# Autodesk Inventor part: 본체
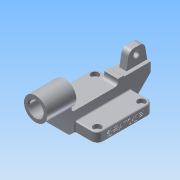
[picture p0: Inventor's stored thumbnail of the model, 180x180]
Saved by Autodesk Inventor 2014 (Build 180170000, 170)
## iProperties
Created: 2017-10
Part Number: 본체
Material: 알루미늄 6061
Document SubType Name: Modeling
Designer: mduedu
Density: 2.71 g/cm^3
Mass: 97.8104 g
Surface Area: 126.629 cm^2
Volume: 36.0924 cm^3
Appearance: 알루미늄 - 평지
Author: mduedu
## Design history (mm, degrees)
sketch "스케치1"
  geometry: L1 (0, 0)-(-90, 0); L2 (-90, 0)-(-90, 20); L3 (-90, 20)-(0, 20); L4 (0, 20)-(0, 0)
  constraints: 8 end point, 2 parallel, 1 horizontal, 1 perpendicular
  dimensions: "d0" = 90 distance of L2.end L3.end; "d2" = 20 distance of L1.end L2.end
extrude "돌출1" new body sketch "스케치1" stored distance "d3" = 12; taper "d4" = 0 deg
chamfer "모따기1" distance "d5" = 20; stored, may be unused: second distance "d6" = 2, angle "d7" = 45 deg
chamfer "모따기2" distance "d8" = 12; stored, may be unused: second distance "d9" = 2, angle "d10" = 45 deg
sketch "스케치2"
  geometry: L1 (5, 31)-(53, 31); L2 (53, 31)-(53, -19); L3 (53, -19)-(5, -19); L4 (5, -19)-(5, 31); L5 (58, 12)-(58, 0) reference; L6 (0, 0)-(0, 12) reference; 2 further points
  constraints: 8 end point, 2 parallel, 1 horizontal, 1 horizontal alignment, 1 midpoint, 1 perpendicular
  dimensions: "d11" = 5 distance between parallel lines of L2 L5; "d12" = 5 distance between parallel lines of L4 L6; "d13" = 50 distance of L1.end L2.end
extrude "돌출2" join sketch "스케치2" distance "d14" = 8; taper "d15" = 0 deg
sketch "스케치3"
  geometry: L1 (0, 20)-(-90, 20) reference; L2 (-28, 20)-(-68, 20); L3 (-68, 20)-(-68, 16); L4 (-68, 16)-(-28, 16); L5 (-28, 16)-(-28, 20); L6 (0, 20)-(0, 12) reference; 1 further point
  constraints: 8 end point, 2 parallel, 1 horizontal, 1 perpendicular, 1 point on line
  dimensions: "d16" = 40 distance of L2.start L2.end; "d18" = 4 distance of L4.end L2.start; "d19" = 28 distance between parallel lines of L5 L6
extrude "돌출3" cut sketch "스케치3" stored distance "d20" = 10; taper "d21" = 0 deg
sketch "스케치4"
  geometry: L1 (0, -16)-(12, -16) reference; L2 (0, 4)-(12, 4) reference; C1 r 10 at (6, 12); 2 further points
  constraints: 1 centre point, 1 midpoint, 1 vertical alignment
  dimensions: "d22" = 20 diameter of C1; "d23" = 8 distance from line of C1.centre L2
extrude "돌출4" join sketch "스케치4" distance "d24" = 25; taper "d25" = 0 deg
sketch "스케치5"
  geometry: L1 (0, 20)-(-28, 20) reference; L2 (0, 20)-(-18, 20); L3 (-18, 20)-(-18, 34); L4 (-18, 34)-(0, 34); L5 (0, 34)-(0, 20); 1 further point
  constraints: 8 end point, 2 parallel, 1 horizontal, 1 perpendicular
  dimensions: "d26" = 18 distance of L3.end L4.end; "d28" = 14 distance of L4.end L1.start
extrude "돌출5" join sketch "스케치5" stored distance "d29" = 6; taper "d30" = 0 deg
sketch "스케치6"
  geometry: L1 (28, -9)-(10, -9) reference; L2 (10, -9)-(10, -3) reference; L3 (10, -3)-(28, -3) reference; L4 (28, -3)-(28, 0) reference; L5 (0, 0)-(28, 0) reference; L6 (0, 0)-(0, -12) reference; L7 (28, -12)-(0, -12) reference; L8 (28, -12)-(28, -9) reference; L9 (28, -9)-(28, -3) reference; 1 further point
  node "투영된 루프1"
feature "면 기울기1" dims angle "d31" = 10 deg
feature "면 기울기2" dims angle "d32" = 10 deg, "d33" = 0
fillet "모깎기1" dims "d34" = 5
sketch "스케치7"
  geometry: L1 (-6.664, 34)-(-11.336, 34) reference; L2 (0, 20)-(-28, 20) reference; L3 (-9, 34)-(-9, 20); C1 r 2.5 at (-9, 28); 1 further point
  constraints: 2 end point, 2 point on line, 1 centre point, 1 midpoint, 1 perpendicular
  dimensions: "d35" = 5 diameter of C1; "d36" = 8 distance from line of L2 C1.centre
extrude "돌출6" cut sketch "스케치7" stored distance "d37" = 6; taper "d38" = 0 deg
sketch "스케치8"
  geometry: C1 r 6 at (6, 12); A1 r 10 centre (6, 12) between (12, 4) and (0, 4) reference; 1 further point
  constraints: 1 centre point, 1 coincident
  dimensions: "d39" = 12 diameter of C1
extrude "돌출7" cut sketch "스케치8" stored distance "d40" = 6; taper "d41" = 0 deg
chamfer "모따기3" distance "d42" = 1; stored, may be unused: second distance "d43" = 2, angle "d44" = 45 deg
chamfer "모따기4" distance "d45" = 0.5; stored, may be unused: second distance "d46" = 2, angle "d47" = 45 deg
fillet "모깎기2" dims "d48" = 2, "d49" = 3
fillet "모깎기3" dims "d50" = 5
fillet "모깎기4" dims "d51" = 3
sketch "스케치9"
  geometry: L1 (0, 12)-(0, 0) reference; L2 (0, 12)-(5, 12); L3 (5, 12)-(5, 0); L4 (5, 0)-(0, 0); L5 (0, 0)-(0, 12); 1 further point
  constraints: 8 end point, 2 parallel, 1 horizontal, 1 perpendicular
  dimensions: "d52" = 5 distance of L1.start L2.end
extrude "돌출8" join sketch "스케치9" distance "d53" = 1; taper "d54" = 0 deg
fillet "모깎기5" dims "d55" = 0.5
sketch "스케치10"
  geometry: A1 r 5 centre (10, 14) between (10, 19) and (5, 14) reference; A2 r 5 centre (48, 14) between (53, 14) and (48, 19) reference; A3 r 5 centre (48, -26) between (48, -31) and (53, -26) reference; A4 r 5 centre (10, -26) between (5, -26) and (10, -31) reference; 5 further points
  constraints: 4 coincident
sketch "스케치11"
  geometry: A1 r 5 centre (10, 14) between (10, 19) and (5, 14) reference; A2 r 5 centre (48, 14) between (53, 14) and (48, 19) reference; A3 r 5 centre (48, -26) between (48, -31) and (53, -26) reference; A4 r 5 centre (10, -26) between (5, -26) and (10, -31) reference; A5 r 5 centre (10, 14) between (10, 19) and (5, 14) reference; 4 further points
  constraints: 4 coincident
hole "구멍1" sketch "스케치11" at (10, 14), (48, 14), (48, -26), (10, -26) diameter "d56" = 3.4; stored, may be unused: countersink angle "d60" = 90 deg, drill point angle "d62" = 0 deg; dims "d57" = 6, "d58" = 6.5, "d59" = 3.4, "d61" = 8
fillet "모깎기6" dims "d63" = 1
fillet "모깎기7" dims "d64" = 1
sketch "스케치12"
  geometry: L1 (0, 0)-(0, 7) reference; L2 (38, 7)-(38, 0) reference; L3 (0, 3.5)-(38, 3.5); 3 further points
  constraints: 3 midpoint, 2 end point, 1 coincident, 1 other
feature "엠보싱1" sketch "스케치12" dims "d0" = 90, "d2" = 20, "d65" = 0.5, "d66" = 0
node "솔리드1"
